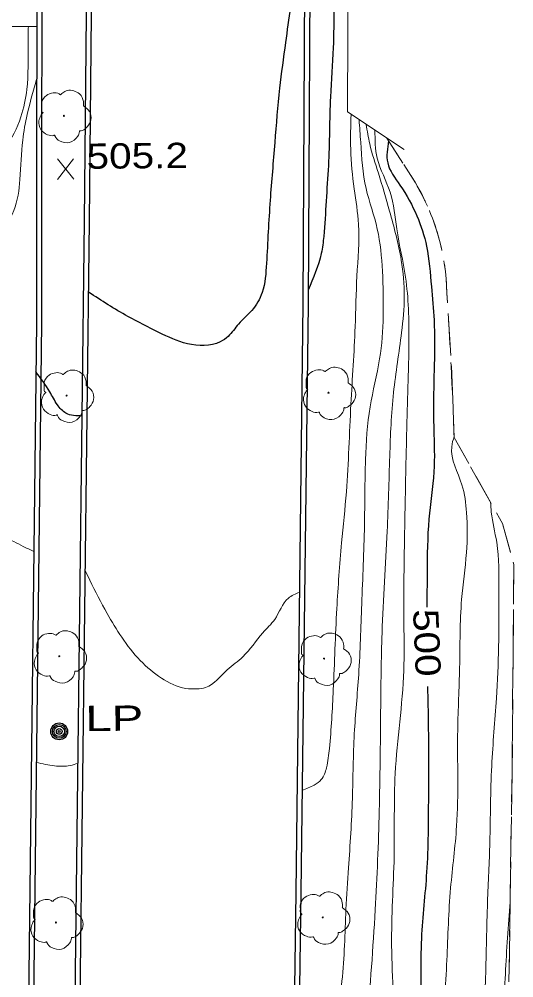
# Model space of a CAD drawing. Extents: x 2362213 to 2366494, y 6968794 to 6978110.
# Drawn here: x 2364221.8 to 2364315.8, y 6975076.1 to 6975258.2 of the extents above; entities that cross this region are included whole.
import ezdxf
from ezdxf.enums import TextEntityAlignment as Align

# ---------------------------------------------------------------- set-up
doc = ezdxf.new("R2010")
doc.units = 0
doc.header["$LTSCALE"] = 1.9
doc.linetypes.add('MEDIUM_DASHED', pattern=[4.5, 3, -1.5])
for name, color, linetype, lineweight in [('2', 7, 'Continuous', 25), ('20', 7, 'Continuous', 25), ('28', 7, 'Continuous', 13), ('29', 7, 'Continuous', 13), ('31', 7, 'Continuous', 25), ('35', 7, 'Continuous', 13), ('9', 7, 'Continuous', 13)]:
    doc.layers.add(name, color=color, linetype=linetype, lineweight=lineweight)

msp = doc.modelspace()

# ---------------------------------------------------------------- linework, layer by layer
at = {"layer": '2'}
for p, q in [((2364231.307, 6974979.053), (2364234.195, 6975219.863)), ((2364232.268, 6974979.043), (2364235.154, 6975219.852))]:
    msp.add_line(p, q, dxfattribs=at)
for points in [[(2364223.776, 6975400.272), (2364223.163, 6975293.391), (2364225.155, 6975293.19), (2364225.057, 6975200.565), (2364223.616, 6975076.795), (2364222.629, 6974979.891)], [(2364224.734, 6975399.441), (2364224.125, 6975294.26), (2364226.117, 6975294.059), (2364226.018, 6975200.554), (2364224.576, 6975076.784), (2364223.589, 6974979.88)], [(2364234.195, 6975219.863), (2364235.168, 6975318.197), (2364236.085, 6975398.299)], [(2364235.154, 6975219.852), (2364236.128, 6975318.186), (2364237.056, 6975399.208)], [(2364276.16, 6975288.836), (2364275.716, 6975204.178), (2364274.351, 6975092.289), (2364272.901, 6974988.33), (2364271.667, 6974863.732), (2364270.321, 6974746.693)], [(2364277.12, 6975288.835), (2364276.676, 6975204.167), (2364275.311, 6975092.279), (2364273.861, 6974988.319), (2364272.627, 6974863.721), (2364271.282, 6974746.683)]]:
    msp.add_lwpolyline(points, dxfattribs=at)
at = {"layer": '20'}
for radius in [1.6, 1.3, 1, 0.539, 0.192]:
    msp.add_circle((2364229.397, 6975122.912), radius, dxfattribs=at)
at = {"layer": '28', "linetype": 'MEDIUM_DASHED'}
msp.add_line((2364291.636, 6975235.65), (2364297.067, 6975227.162), dxfattribs=at)
at = {"layer": '28'}
for p, q in [((2364291.636, 6975235.65), (2364293.789, 6975232.28)), ((2364303.295, 6975202.33), (2364303.791, 6975194.343)), ((2364303.91, 6975192.344), (2364304.226, 6975184.348)), ((2364307.572, 6975173.178), (2364311.499, 6975166.206)), ((2364315.7, 6975145.065), (2364315.636, 6975137.065)), ((2364315.615, 6975135.064), (2364315.551, 6975127.062)), ((2364315.53, 6975125.062), (2364315.467, 6975117.061)), ((2364315.456, 6975115.062), (2364315.332, 6975107.059)), ((2364315.301, 6975105.059), (2364315.177, 6975097.057)), ((2364315.146, 6975095.057), (2364315.022, 6975087.056)), ((2364314.991, 6975085.055), (2364314.868, 6975077.054))]:
    msp.add_line(p, q, dxfattribs=at)
for points in [[(2364294.865, 6975230.601), (2364297.067, 6975227.162), (2364297.444, 6975226.515), (2364297.811, 6975225.869), (2364298.157, 6975225.212), (2364298.503, 6975224.545), (2364298.83, 6975223.868), (2364298.911, 6975223.709)], [(2364299.729, 6975221.887), (2364299.749, 6975221.827), (2364300.026, 6975221.14), (2364300.303, 6975220.442), (2364300.559, 6975219.745), (2364300.806, 6975219.036), (2364301.033, 6975218.328), (2364301.259, 6975217.62), (2364301.466, 6975216.902), (2364301.663, 6975216.184), (2364301.84, 6975215.456), (2364302.017, 6975214.727), (2364302.122, 6975214.258)], [(2364302.49, 6975212.292), (2364302.565, 6975211.793), (2364302.672, 6975211.064), (2364302.769, 6975210.324), (2364302.846, 6975209.575), (2364302.913, 6975208.837), (2364302.97, 6975208.087), (2364303.007, 6975207.348), (2364303.035, 6975206.598), (2364303.049, 6975206.148), (2364303.166, 6975204.329)], [(2364304.305, 6975182.349), (2364304.411, 6975179.66), (2364304.43, 6975178.76), (2364306.595, 6975174.919)], [(2364312.475, 6975164.465), (2364313.645, 6975162.387), (2364315.137, 6975156.971)], [(2364315.665, 6975155.046), (2364315.779, 6975154.637), (2364315.721, 6975147.065)]]:
    msp.add_lwpolyline(points, dxfattribs=at)
at = {"layer": '28', "linetype": 'MEDIUM_DASHED'}
msp.add_lwpolyline([(2364304.43, 6975178.76), (2364313.645, 6975162.387), (2364315.779, 6975154.637), (2364315.454, 6975115.242), (2364314.585, 6975058.46), (2364313.622, 6974976.837), (2364312.143, 6974886.428), (2364311.627, 6974777.839), (2364311.092, 6974745.792)], dxfattribs=at)
for centre, radius, start, end in [((2364260.295, 6975205.338), 42.761, 1.08428, 30.68731), ((2363544.9, 6975154.194), 759.926, 1.85248, 3.92018)]:
    msp.add_arc(centre, radius, start, end, dxfattribs=at)
at = {"layer": '29'}
for centre in [(2364230.294, 6975239.866), (2364280.567, 6975187.262), (2364230.8, 6975186.718), (2364229.421, 6975137.183), (2364279.718, 6975136.742), (2364279.476, 6975087.567), (2364228.783, 6975086.604)]:
    msp.add_circle(centre, 0.1, dxfattribs=at)
for points in [[(2364226.328, 6975240.438), (2364226.348, 6975240.448), (2364226.267, 6975240.517), (2364226.031, 6975241.145), (2364226.069, 6975242.426), (2364226.957, 6975243.725), (2364228.262, 6975244.207), (2364229.384, 6975244.018), (2364229.615, 6975243.89), (2364229.685, 6975243.891), (2364229.735, 6975243.931), (2364230.082, 6975244.225), (2364230.948, 6975244.673), (2364232.159, 6975244.605), (2364233.275, 6975244.015), (2364234.009, 6975242.592), (2364234.017, 6975241.731)], [(2364234.007, 6975241.751), (2364235.146, 6975240.692), (2364235.431, 6975239.104), (2364234.725, 6975237.778), (2364234.07, 6975237.231), (2364233.402, 6975237.015), (2364233.252, 6975237.004), (2364233.233, 6975236.893), (2364232.911, 6975235.99), (2364231.371, 6975234.826), (2364229.479, 6975235.108), (2364228.58, 6975236.049), (2364228.508, 6975236.178), (2364228.389, 6975236.157), (2364227.177, 6975236.276), (2364225.908, 6975237.274), (2364225.562, 6975238.911), (2364225.933, 6975239.934), (2364226.258, 6975240.377), (2364226.328, 6975240.428)], [(2364226.834, 6975187.29), (2364226.854, 6975187.3), (2364226.773, 6975187.37), (2364226.537, 6975187.997), (2364226.575, 6975189.278), (2364227.463, 6975190.576), (2364228.768, 6975191.059), (2364229.89, 6975190.87), (2364230.121, 6975190.742), (2364230.191, 6975190.742), (2364230.241, 6975190.783), (2364230.588, 6975191.076), (2364231.455, 6975191.524), (2364232.666, 6975191.456), (2364233.781, 6975190.867), (2364234.515, 6975189.444), (2364234.523, 6975188.584)], [(2364276.602, 6975187.834), (2364276.622, 6975187.844), (2364276.541, 6975187.914), (2364276.305, 6975188.541), (2364276.343, 6975189.822), (2364277.231, 6975191.12), (2364278.536, 6975191.603), (2364279.658, 6975191.413), (2364279.889, 6975191.286), (2364279.959, 6975191.286), (2364280.009, 6975191.327), (2364280.356, 6975191.62), (2364281.222, 6975192.068), (2364282.432, 6975192), (2364283.547, 6975191.41), (2364284.281, 6975189.987), (2364284.289, 6975189.127)], [(2364284.279, 6975189.147), (2364285.419, 6975188.088), (2364285.704, 6975186.501), (2364284.997, 6975185.175), (2364284.342, 6975184.629), (2364283.674, 6975184.412), (2364283.524, 6975184.401), (2364283.505, 6975184.291), (2364283.184, 6975183.388), (2364281.646, 6975182.223), (2364279.753, 6975182.505), (2364278.854, 6975183.446), (2364278.783, 6975183.576), (2364278.663, 6975183.555), (2364277.452, 6975183.673), (2364276.182, 6975184.671), (2364275.837, 6975186.307), (2364276.207, 6975187.33), (2364276.533, 6975187.774), (2364276.602, 6975187.824)], [(2364234.513, 6975188.603), (2364235.652, 6975187.544), (2364235.937, 6975185.957), (2364235.231, 6975184.631), (2364234.576, 6975184.085), (2364233.908, 6975183.868), (2364233.758, 6975183.857), (2364233.739, 6975183.747), (2364233.418, 6975182.844), (2364231.879, 6975181.679), (2364229.985, 6975181.961), (2364229.086, 6975182.903), (2364229.015, 6975183.032), (2364228.895, 6975183.011), (2364227.684, 6975183.129), (2364226.414, 6975184.127), (2364226.068, 6975185.763), (2364226.439, 6975186.786), (2364226.764, 6975187.23), (2364226.834, 6975187.28)], [(2364225.456, 6975137.756), (2364225.475, 6975137.766), (2364225.395, 6975137.835), (2364225.159, 6975138.463), (2364225.197, 6975139.743), (2364226.084, 6975141.041), (2364227.39, 6975141.523), (2364228.512, 6975141.334), (2364228.743, 6975141.206), (2364228.813, 6975141.207), (2364228.862, 6975141.248), (2364229.21, 6975141.541), (2364230.075, 6975141.989), (2364231.286, 6975141.921), (2364232.403, 6975141.331), (2364233.136, 6975139.908), (2364233.145, 6975139.048)], [(2364275.753, 6975137.315), (2364275.773, 6975137.325), (2364275.692, 6975137.394), (2364275.455, 6975138.022), (2364275.493, 6975139.301), (2364276.382, 6975140.6), (2364277.687, 6975141.082), (2364278.809, 6975140.893), (2364279.04, 6975140.765), (2364279.11, 6975140.766), (2364279.16, 6975140.806), (2364279.507, 6975141.1), (2364280.373, 6975141.548), (2364281.584, 6975141.48), (2364282.698, 6975140.89), (2364283.432, 6975139.467), (2364283.44, 6975138.608)], [(2364233.134, 6975139.068), (2364234.275, 6975138.01), (2364234.56, 6975136.423), (2364233.852, 6975135.096), (2364233.197, 6975134.549), (2364232.529, 6975134.333), (2364232.38, 6975134.322), (2364232.361, 6975134.211), (2364232.039, 6975133.308), (2364230.499, 6975132.144), (2364228.606, 6975132.426), (2364227.707, 6975133.367), (2364227.636, 6975133.496), (2364227.516, 6975133.475), (2364226.305, 6975133.594), (2364225.036, 6975134.592), (2364224.69, 6975136.229), (2364225.06, 6975137.252), (2364225.386, 6975137.695), (2364225.456, 6975137.746)], [(2364283.43, 6975138.628), (2364284.57, 6975137.569), (2364284.855, 6975135.981), (2364284.148, 6975134.655), (2364283.493, 6975134.108), (2364282.825, 6975133.892), (2364282.675, 6975133.881), (2364282.656, 6975133.77), (2364282.336, 6975132.867), (2364280.797, 6975131.703), (2364278.904, 6975131.985), (2364278.005, 6975132.926), (2364277.934, 6975133.055), (2364277.814, 6975133.034), (2364276.603, 6975133.153), (2364275.332, 6975134.151), (2364274.987, 6975135.787), (2364275.357, 6975136.811), (2364275.684, 6975137.254), (2364275.753, 6975137.305)], [(2364275.51, 6975088.14), (2364275.53, 6975088.15), (2364275.45, 6975088.22), (2364275.214, 6975088.847), (2364275.251, 6975090.128), (2364276.14, 6975091.426), (2364277.445, 6975091.909), (2364278.567, 6975091.72), (2364278.799, 6975091.592), (2364278.869, 6975091.592), (2364278.918, 6975091.633), (2364279.265, 6975091.926), (2364280.131, 6975092.374), (2364281.342, 6975092.306), (2364282.458, 6975091.717), (2364283.19, 6975090.294), (2364283.198, 6975089.434)], [(2364224.817, 6975087.178), (2364224.837, 6975087.188), (2364224.756, 6975087.257), (2364224.52, 6975087.885), (2364224.558, 6975089.165), (2364225.446, 6975090.464), (2364226.751, 6975090.946), (2364227.873, 6975090.757), (2364228.104, 6975090.629), (2364228.174, 6975090.63), (2364228.224, 6975090.67), (2364228.571, 6975090.963), (2364229.437, 6975091.412), (2364230.648, 6975091.343), (2364231.764, 6975090.754), (2364232.498, 6975089.331), (2364232.506, 6975088.471)], [(2364283.188, 6975089.453), (2364284.328, 6975088.394), (2364284.613, 6975086.806), (2364283.906, 6975085.479), (2364283.251, 6975084.933), (2364282.584, 6975084.716), (2364282.434, 6975084.705), (2364282.415, 6975084.595), (2364282.094, 6975083.692), (2364280.555, 6975082.527), (2364278.662, 6975082.809), (2364277.763, 6975083.751), (2364277.692, 6975083.88), (2364277.572, 6975083.859), (2364276.361, 6975083.977), (2364275.09, 6975084.975), (2364274.745, 6975086.612), (2364275.115, 6975087.637), (2364275.441, 6975088.08), (2364275.51, 6975088.13)], [(2364232.496, 6975088.491), (2364233.636, 6975087.432), (2364233.921, 6975085.843), (2364233.214, 6975084.516), (2364232.559, 6975083.97), (2364231.891, 6975083.754), (2364231.741, 6975083.742), (2364231.722, 6975083.632), (2364231.4, 6975082.729), (2364229.861, 6975081.564), (2364227.968, 6975081.846), (2364227.069, 6975082.788), (2364226.998, 6975082.917), (2364226.878, 6975082.896), (2364225.667, 6975083.014), (2364224.397, 6975084.012), (2364224.052, 6975085.649), (2364224.422, 6975086.673), (2364224.748, 6975087.117), (2364224.817, 6975087.168)]]:
    msp.add_spline(points, degree=3, dxfattribs=at)
at = {"layer": '31', "lineweight": 13}
for p, q in [((2364232.169, 6975227.824), (2364229.051, 6975231.673)), ((2364229.088, 6975227.795), (2364232.132, 6975231.703))]:
    msp.add_line(p, q, dxfattribs=at)
at = {"layer": '31'}
for points in [[(2364280.29, 6975570.208), (2364280.603, 6975568.851), (2364281.649, 6975566.13), (2364282.577, 6975558.999), (2364283.054, 6975551.984), (2364283.384, 6975540.366), (2364283.22, 6975527.164), (2364283.364, 6975513.064), (2364283.203, 6975493.212), (2364282.894, 6975477.358), (2364282.403, 6975454.393), (2364282.255, 6975441.541), (2364282.296, 6975418.419), (2364282.52, 6975402.201), (2364282.543, 6975374.63), (2364282.472, 6975351.538), (2364282.506, 6975330.127), (2364282.448, 6975305.755), (2364282.363, 6975289.525), (2364281.942, 6975274.95), (2364281.857, 6975273.349), (2364281.665, 6975268.257), (2364281.453, 6975252.794), (2364280.932, 6975243.479), (2364280.547, 6975230.405), (2364280.111, 6975223.67), (2364279.665, 6975216.965), (2364279.195, 6975213.74), (2364276.692, 6975206.757)], [(2364276.12, 6975281.554), (2364275.394, 6975276.798), (2364274.325, 6975267.217), (2364273.318, 6975260.566), (2364272.393, 6975253.778), (2364271.255, 6975245.127), (2364270.354, 6975234.787), (2364269.478, 6975223.819), (2364268.782, 6975211.851), (2364267.945, 6975206.284), (2364266.017, 6975202.905), (2364263.472, 6975200.301), (2364261.504, 6975197.962), (2364260.014, 6975196.937), (2364253.758, 6975196.557), (2364248.316, 6975198.726), (2364242.457, 6975201.741), (2364234.994, 6975206.35)], [(2364291.981, 6975235.113), (2364291.811, 6975230.932), (2364294.132, 6975226.704), (2364297.378, 6975220.835), (2364299.193, 6975215.091), (2364300.116, 6975207.43), (2364300.627, 6975201.035), (2364300.667, 6975192.644), (2364300.512, 6975183.733), (2364300.575, 6975180.323), (2364300.602, 6975172.242), (2364299.647, 6975163.223), (2364299.305, 6975152.939), (2364299.246, 6975146.518)], [(2364233.748, 6975182.827), (2364230.681, 6975183.368), (2364229.056, 6975184.982), (2364227.603, 6975187.428), (2364224.946, 6975191.262)], [(2364299.37, 6975131.419), (2364299.52, 6975124.12), (2364299.54, 6975110.47), (2364299.206, 6975096.175), (2364298.226, 6975083.575), (2364298.188, 6975068.635), (2364298.05, 6975055.782), (2364297.668, 6975044.419), (2364296.434, 6975030.096), (2364295.822, 6975017.67), (2364295.334, 6975002.824), (2364294.819, 6974982.258), (2364294.889, 6974967.568), (2364294.998, 6974956.119), (2364295.46, 6974948.583), (2364294.86, 6974927.626), (2364293.833, 6974910.466), (2364293.268, 6974892.089), (2364292.445, 6974870.331), (2364291.325, 6974856.639), (2364289.958, 6974843.806), (2364289.201, 6974830.828), (2364287.742, 6974814.932), (2364286.635, 6974799.992), (2364285.85, 6974783.694), (2364286.008, 6974770.194)]]:
    msp.add_spline(points, degree=3, dxfattribs=at)
at = {"layer": '35'}
for points in [[(2364223.541, 6975256.862), (2364223.484, 6975253.462), (2364223.245, 6975244.89), (2364222.125, 6975239.658), (2364219.101, 6975233.799), (2364215.513, 6975230.365), (2364209.532, 6975226.338), (2364204.126, 6975223.737), (2364198.564, 6975221.824), (2364193.092, 6975219.911), (2364181.858, 6975216.003), (2364174.424, 6975215.412), (2364162.075, 6975215.255), (2364142.939, 6975216.703), (2364130.821, 6975216.557)], [(2364224.551, 6975157.108), (2364222.542, 6975158.059), (2364220.773, 6975158.972), (2364218.32, 6975160.309), (2364216.84, 6975163.524), (2364216.129, 6975166.737), (2364214.441, 6975169.731), (2364212.275, 6975175.612), (2364211.481, 6975179.195), (2364210.172, 6975184.412), (2364208.243, 6975188.373), (2364205.053, 6975192.573), (2364199.884, 6975197.705), (2364197.644, 6975200.824), (2364196.207, 6975204.7), (2364196.195, 6975206.97), (2364197.996, 6975208.987), (2364202.465, 6975212.289), (2364209.596, 6975214.397), (2364216.922, 6975216.797), (2364220.775, 6975221.855), (2364221.938, 6975227.786), (2364222.467, 6975235.251), (2364223.321, 6975240.119), (2364225.107, 6975246.828)], [(2364284.853, 6975240.145), (2364284.786, 6975233.524), (2364285.448, 6975225.991), (2364286.262, 6975219.228), (2364285.966, 6975209.404), (2364285.637, 6975199.812), (2364284.828, 6975185.053), (2364283.956, 6975168.443), (2364283.068, 6975158.735), (2364282.148, 6975146.265), (2364281.475, 6975130.818), (2364280.741, 6975119.681), (2364280.186, 6975116.005), (2364279.188, 6975113.746), (2364277.867, 6975112.714), (2364275.546, 6975111.712)], [(2364287.731, 6975238.242), (2364288.397, 6975234.559), (2364290.04, 6975228.985), (2364292.159, 6975221.755), (2364294.387, 6975212.465), (2364294.963, 6975205.531), (2364294.448, 6975198.716), (2364292.927, 6975187.27), (2364292.202, 6975175.202), (2364291.727, 6975160.978), (2364290.741, 6975141.647), (2364290.474, 6975126.704), (2364290.203, 6975107.85), (2364289.452, 6975089.023), (2364287.999, 6975067.348), (2364287.33, 6975054.65), (2364286.463, 6975033.341), (2364285.661, 6975015.653), (2364284.784, 6974996.403), (2364283.572, 6974976.751), (2364282.93, 6974962.244), (2364281.925, 6974950.164), (2364281.29, 6974940.248), (2364280.433, 6974931.508), (2364279.074, 6974925.056), (2364277.441, 6974922.21), (2364273.191, 6974921.06)], [(2364286.383, 6975239.13), (2364286.684, 6975234.842), (2364287.707, 6975226.073), (2364289.841, 6975218.352), (2364290.807, 6975210.35), (2364290.958, 6975201.823), (2364290.286, 6975193.685), (2364288.473, 6975184.568), (2364287.598, 6975174.538), (2364287.397, 6975162.067), (2364286.88, 6975147.07), (2364286.307, 6975133.715), (2364285.474, 6975122.476), (2364285.101, 6975110.133), (2364284.376, 6975097.014), (2364283.872, 6975089.09), (2364283.101, 6975075.451), (2364281.471, 6975064.075), (2364281.156, 6975053.021), (2364280.737, 6975046.637), (2364279.617, 6975041.336), (2364278.802, 6975039.768), (2364274.525, 6975036.208)], [(2364289.392, 6975237.138), (2364289.833, 6975231.793), (2364292.265, 6975225.346), (2364293.531, 6975218.387), (2364295.208, 6975209.192), (2364295.746, 6975203.188), (2364295.725, 6975190.616), (2364295.47, 6975181.725), (2364295.197, 6975169.46), (2364294.976, 6975157.969), (2364294.896, 6975143.336), (2364294.88, 6975134.497), (2364293.246, 6975114.9), (2364293.036, 6975099.187), (2364292.557, 6975082.211), (2364292.956, 6975063.494), (2364292.025, 6975052.005), (2364292.086, 6975038.285), (2364291.392, 6975027.148), (2364290.246, 6975014.086), (2364289.34, 6975001.097), (2364288.481, 6974985.188), (2364288.061, 6974968.423), (2364287.9, 6974949.621), (2364287.109, 6974930.752), (2364286.564, 6974923.937), (2364285.331, 6974909.614), (2364284.521, 6974887.585), (2364283.475, 6974874.625), (2364282.504, 6974865.255), (2364281.55, 6974848.896), (2364280.759, 6974838.487), (2364280.49, 6974821.554), (2364280.309, 6974814.272), (2364279.906, 6974808.338), (2364279.488, 6974794.463), (2364278.841, 6974786.807), (2364279.178, 6974779.76), (2364278.851, 6974776.296), (2364277.459, 6974775.443), (2364275.666, 6974775.686), (2364274.43, 6974777.314), (2364273.306, 6974781.974), (2364271.872, 6974798.13)], [(2364304.428, 6975178.93), (2364303.976, 6975176.995), (2364305.914, 6975169.763), (2364306.805, 6975164.501), (2364306.777, 6975156.871), (2364305.862, 6975148.001), (2364305.476, 6975135.028), (2364305.119, 6975123.213), (2364304.903, 6975104.92), (2364303.775, 6975093.179), (2364303.045, 6975079.471), (2364302.375, 6975064.784), (2364302.424, 6975044.905), (2364301.932, 6975020.999), (2364300.899, 6975000.247), (2364300.079, 6974980.368), (2364299.948, 6974961.566), (2364299.287, 6974939.529), (2364298.923, 6974924.235), (2364298.125, 6974892.486), (2364296.454, 6974869.369), (2364294.927, 6974837.622), (2364293.392, 6974810.827), (2364292.503, 6974785.477), (2364290.749, 6974746.028)], [(2364311.356, 6975166.454), (2364311.504, 6975164.575), (2364312.519, 6975158.836), (2364312.937, 6975149.588), (2364312.888, 6975138.999), (2364312.491, 6975129.203), (2364311.573, 6975116.354), (2364311.222, 6975101.82), (2364310.78, 6975090.456), (2364310.406, 6975076.161), (2364309.862, 6975062.875), (2364308.858, 6975043.406), (2364307.934, 6975028.055), (2364307.189, 6975004.417), (2364306.155, 6974989.167), (2364305.37, 6974967.618), (2364303.611, 6974941.23), (2364303.75, 6974924.551), (2364303.837, 6974910.211), (2364302.574, 6974893.688), (2364301.052, 6974875.003), (2364300.489, 6974856.397), (2364298.441, 6974833.096), (2364296.874, 6974812.73), (2364296.399, 6974797.494), (2364295.644, 6974775.956), (2364295.239, 6974762.772), (2364294.719, 6974746.046)], [(2364275.047, 6975149.338), (2364272.948, 6975148.218), (2364270.346, 6975144.193), (2364268.081, 6975141.631), (2364264.313, 6975137.106), (2364261.307, 6975134.587), (2364257.22, 6975131.268), (2364255.562, 6975130.991), (2364253.43, 6975131.091), (2364248.832, 6975133.038), (2364244.81, 6975136.37), (2364241.297, 6975140.796), (2364238.514, 6975145.33), (2364235.215, 6975151.638), (2364234.358, 6975153.421)], [(2364232.956, 6975116.825), (2364231.49, 6975116.441), (2364228.529, 6975116.363), (2364225.043, 6975117.02)], [(2364315.08, 6975090.507), (2364314.584, 6975083.701), (2364313.916, 6975069.884), (2364313.667, 6975055.111), (2364313.149, 6975040.196), (2364312.647, 6975027.71), (2364312.402, 6975015.717), (2364312.013, 6975002.993), (2364311.786, 6974984.78), (2364310.98, 6974973.852), (2364310.685, 6974957.538), (2364310.761, 6974938.048), (2364309.985, 6974927.15), (2364309.737, 6974913.217), (2364308.89, 6974896.158), (2364308.279, 6974883.672), (2364306.695, 6974868.426), (2364305.982, 6974846.679), (2364304.462, 6974826.703), (2364304.305, 6974817.96), (2364304.007, 6974799.908), (2364303.278, 6974784.07), (2364302.83, 6974769.184), (2364302.6, 6974758.702), (2364302.014, 6974745.625)]]:
    msp.add_spline(points, degree=3, dxfattribs=at)
at = {"layer": '9'}
msp.add_line((2364214.651, 6975256.857), (2364225.121, 6975256.867), dxfattribs=at)
msp.add_lwpolyline([(2364294.511, 6975265.679), (2364284.322, 6975270.762), (2364284.169, 6975240.599), (2364294.957, 6975233.451)], dxfattribs=at)

# ---------------------------------------------------------------- texts
at = {"layer": '20', "width": 1.4}
msp.add_text('  LP', height=4.8, rotation=0.546, dxfattribs=at).set_placement((2364229.397, 6975122.912))
at = {"layer": '31', "width": 1.2}
msp.add_text('505.2', height=4.8, rotation=0.546, dxfattribs=at).set_placement((2364234.611, 6975229.787))
msp.add_text(' 500 ', height=4.8, rotation=272.396, dxfattribs=at).set_placement((2364296.891, 6975139.65), align=Align.CENTER)

doc.saveas('drawing.dxf')
